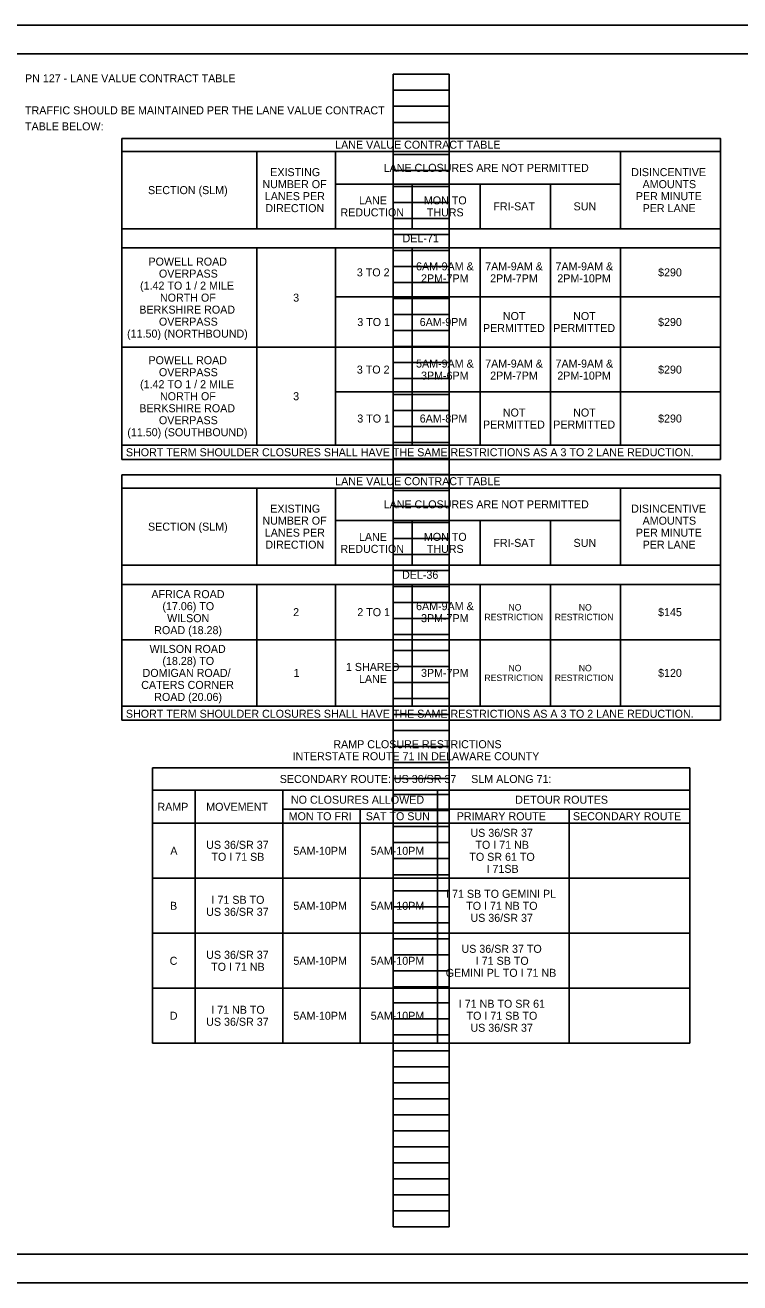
# Model space of a CAD drawing. Extents: x 0 to 34, y 0 to 22.
# Drawn here: x 9.82 to 22.33, y 0 to 22 of the extents above; entities that cross this region are included whole.
import ezdxf

# ---------------------------------------------------------------- set-up
doc = ezdxf.new("R2010")
doc.units = 0
for name, color, linetype in [('Default', 7, 'Continuous'), ('SH_Border', 7, 'Continuous'), ('SH_Cut_Line', 7, 'Continuous'), ('SH_Data', 7, 'Continuous')]:
    doc.layers.add(name, color=color, linetype=linetype)

msp = doc.modelspace()

# ---------------------------------------------------------------- linework, layer by layer
at = {"layer": 'Default'}
for p, q in [((11.511, 19.789), (21.989, 19.789)), ((13.878, 19.789), (13.878, 18.44)), ((15.254, 19.789), (15.254, 18.44)), ((20.242, 19.789), (20.242, 18.44)), ((15.254, 19.22), (20.242, 19.22)), ((16.593, 19.22), (16.593, 18.44)), ((17.783, 19.22), (17.783, 18.44)), ((19.012, 19.22), (19.012, 18.44)), ((11.511, 18.44), (21.989, 18.44)), ((11.511, 18.103), (11.511, 14.404)), ((13.878, 18.103), (13.878, 14.653)), ((15.254, 18.103), (15.254, 14.653)), ((16.593, 18.103), (16.593, 14.653)), ((17.783, 18.103), (17.783, 14.653)), ((19.012, 18.103), (19.012, 14.653)), ((20.242, 18.103), (20.242, 14.653)), ((21.989, 18.103), (21.989, 14.404)), ((15.254, 17.249), (21.989, 17.249)), ((11.511, 16.365), (21.989, 16.365)), ((15.254, 15.585), (21.989, 15.585)), ((11.511, 14.653), (21.989, 14.653)), ((11.511, 14.404), (21.989, 14.404)), ((11.511, 13.903), (21.989, 13.903)), ((13.878, 13.903), (13.878, 12.554)), ((15.254, 13.903), (15.254, 12.554)), ((20.242, 13.903), (20.242, 12.554)), ((15.254, 13.333), (20.242, 13.333)), ((16.593, 13.333), (16.593, 12.554)), ((17.783, 13.333), (17.783, 12.554)), ((19.012, 13.333), (19.012, 12.554)), ((11.511, 12.554), (21.989, 12.554)), ((11.511, 12.217), (11.511, 9.841)), ((11.511, 12.217), (21.989, 12.217)), ((13.878, 12.217), (13.878, 10.09)), ((15.254, 12.217), (15.254, 10.09)), ((16.593, 12.217), (16.593, 10.09)), ((17.783, 12.217), (17.783, 10.09)), ((19.012, 12.217), (19.012, 10.09)), ((20.242, 12.217), (20.242, 10.09)), ((21.989, 12.217), (21.989, 9.841)), ((11.511, 11.247), (21.989, 11.247)), ((11.511, 10.09), (21.989, 10.09)), ((11.511, 10.09), (21.989, 10.09)), ((11.511, 9.841), (21.989, 9.841)), ((12.049, 9.011), (21.451, 9.011)), ((12.049, 4.191), (12.049, 9.011)), ((21.451, 9.011), (21.451, 4.191)), ((12.049, 8.617), (21.451, 8.617)), ((12.795, 8.617), (12.795, 4.191)), ((14.333, 8.617), (14.333, 4.191)), ((17.038, 8.617), (17.038, 4.191)), ((14.333, 8.286), (21.451, 8.286)), ((15.686, 8.286), (15.686, 4.191)), ((17.038, 8.286), (17.038, 4.191)), ((19.339, 8.286), (19.339, 4.191)), ((12.049, 8.038), (21.451, 8.038)), ((12.049, 7.076), (21.451, 7.076)), ((12.049, 6.114), (21.451, 6.114)), ((12.049, 5.152), (21.451, 5.152)), ((12.049, 4.191), (21.451, 4.191))]:
    msp.add_line(p, q, dxfattribs=at)
for points in [[(11.511, 20.02), (21.989, 20.02), (21.989, 18.103), (11.511, 18.103)], [(11.511, 14.134), (21.989, 14.134), (21.989, 12.217), (11.511, 12.217)]]:
    msp.add_lwpolyline(points, close=True, dxfattribs=at)
at = {"layer": 'SH_Border'}
msp.add_lwpolyline([(1.5, 21.5), (33.5, 21.5), (33.5, 0.5), (1.5, 0.5)], close=True, dxfattribs=at)
at = {"layer": 'SH_Cut_Line'}
msp.add_lwpolyline([(0, 0), (34, 0), (34, 22), (0, 22)], close=True, dxfattribs=at)
at = {"layer": 'SH_Data'}
for p, q in [((16.26, 0.98), (16.26, 21.14)), ((16.26, 21.14), (17.24, 21.14)), ((17.24, 0.98), (17.24, 21.14)), ((16.26, 20.86), (17.24, 20.86)), ((16.26, 20.58), (17.24, 20.58)), ((16.26, 20.3), (17.24, 20.3)), ((16.26, 20.02), (17.24, 20.02)), ((16.26, 19.74), (17.24, 19.74)), ((16.26, 19.46), (17.24, 19.46)), ((16.26, 19.18), (17.24, 19.18)), ((16.26, 18.9), (17.24, 18.9)), ((16.26, 18.62), (17.24, 18.62)), ((16.26, 18.34), (17.24, 18.34)), ((16.26, 18.06), (17.24, 18.06)), ((16.26, 17.78), (17.24, 17.78)), ((16.26, 17.5), (17.24, 17.5)), ((16.26, 17.22), (17.24, 17.22)), ((16.26, 16.94), (17.24, 16.94)), ((16.26, 16.66), (17.24, 16.66)), ((16.26, 16.38), (17.24, 16.38)), ((16.26, 16.1), (17.24, 16.1)), ((16.26, 15.82), (17.24, 15.82)), ((16.26, 15.54), (17.24, 15.54)), ((16.26, 15.26), (17.24, 15.26)), ((16.26, 14.98), (17.24, 14.98)), ((16.26, 14.7), (17.24, 14.7)), ((16.26, 14.42), (17.24, 14.42)), ((16.26, 14.14), (17.24, 14.14)), ((16.26, 13.86), (17.24, 13.86)), ((16.26, 13.58), (17.24, 13.58)), ((16.26, 13.3), (17.24, 13.3)), ((16.26, 13.02), (17.24, 13.02)), ((16.26, 12.74), (17.24, 12.74)), ((16.26, 12.46), (17.24, 12.46)), ((16.26, 12.18), (17.24, 12.18)), ((16.26, 11.9), (17.24, 11.9)), ((16.26, 11.62), (17.24, 11.62)), ((16.26, 11.34), (17.24, 11.34)), ((16.26, 11.06), (17.24, 11.06)), ((16.26, 10.78), (17.24, 10.78)), ((16.26, 10.5), (17.24, 10.5)), ((16.26, 10.22), (17.24, 10.22)), ((16.26, 9.94), (17.24, 9.94)), ((16.26, 9.66), (17.24, 9.66)), ((16.26, 9.38), (17.24, 9.38)), ((16.26, 9.1), (17.24, 9.1)), ((16.26, 8.82), (17.24, 8.82)), ((16.26, 8.54), (17.24, 8.54)), ((16.26, 8.26), (17.24, 8.26)), ((16.26, 7.98), (17.24, 7.98)), ((16.26, 7.7), (17.24, 7.7)), ((16.26, 7.42), (17.24, 7.42)), ((16.26, 7.14), (17.24, 7.14)), ((16.26, 6.86), (17.24, 6.86)), ((16.26, 6.58), (17.24, 6.58)), ((16.26, 6.3), (17.24, 6.3)), ((16.26, 6.02), (17.24, 6.02)), ((16.26, 5.74), (17.24, 5.74)), ((16.26, 5.46), (17.24, 5.46)), ((16.26, 5.18), (17.24, 5.18)), ((16.26, 4.9), (17.24, 4.9)), ((16.26, 4.62), (17.24, 4.62)), ((16.26, 4.34), (17.24, 4.34)), ((16.26, 4.06), (17.24, 4.06)), ((16.26, 3.78), (17.24, 3.78)), ((16.26, 3.5), (17.24, 3.5)), ((16.26, 3.22), (17.24, 3.22)), ((16.26, 2.94), (17.24, 2.94)), ((16.26, 2.66), (17.24, 2.66)), ((16.26, 2.38), (17.24, 2.38)), ((16.26, 2.1), (17.24, 2.1)), ((16.26, 1.82), (17.24, 1.82)), ((16.26, 1.54), (17.24, 1.54)), ((16.26, 1.26), (17.24, 1.26)), ((16.26, 0.98), (17.24, 0.98))]:
    msp.add_line(p, q, dxfattribs=at)

# ---------------------------------------------------------------- texts
at = {"layer": 'Default'}
for s, height, p in [('PN 127 - LANE VALUE CONTRACT TABLE', 0.14, (9.82, 21)), ('TRAFFIC SHOULD BE MAINTAINED PER THE LANE VALUE CONTRACT', 0.14, (9.82, 20.44)), ('TABLE BELOW:', 0.14, (9.82, 20.16)), ('LANE VALUE CONTRACT TABLE', 0.14, (15.247, 19.839)), ('EXISTING', 0.14, (14.111, 19.359)), ('LANE CLOSURES ARE NOT PERMITTED', 0.14, (16.095, 19.434)), ('DISINCENTIVE', 0.14, (20.426, 19.359)), ('SECTION (SLM)', 0.14, (11.972, 19.044)), ('NUMBER OF', 0.14, (13.974, 19.149)), ('AMOUNTS', 0.14, (20.626, 19.149)), ('LANES PER ', 0.14, (14.016, 18.939)), ('LANE ', 0.14, (15.663, 18.865)), ('MON TO', 0.14, (16.799, 18.865)), ('PER MINUTE', 0.14, (20.508, 18.939)), ('DIRECTION', 0.14, (14.025, 18.729)), ('REDUCTION', 0.14, (15.339, 18.655)), ('THURS', 0.14, (16.85, 18.655)), ('FRI-SAT', 0.14, (18.015, 18.76)), ('SUN', 0.14, (19.418, 18.76)), ('PER LANE', 0.14, (20.627, 18.729)), ('DEL-71', 0.14, (16.426, 18.201)), ('POWELL ROAD', 0.14, (11.98, 17.794)), ('6AM-9AM &', 0.14, (16.662, 17.711)), ('7AM-9AM &', 0.14, (17.872, 17.711)), ('7AM-9AM &', 0.14, (19.102, 17.711)), ('OVERPASS', 0.14, (12.163, 17.584)), ('3 TO 2', 0.14, (15.626, 17.606)), ('2PM-7PM', 0.14, (16.749, 17.501)), ('2PM-7PM', 0.14, (17.959, 17.501)), ('2PM-10PM', 0.14, (19.134, 17.501)), ('$290', 0.14, (20.897, 17.606)), ('(1.42 TO 1 / 2 MILE', 0.14, (11.833, 17.374)), ('NORTH OF', 0.14, (12.181, 17.164)), ('3', 0.14, (14.512, 17.164)), ('BERKSHIRE ROAD', 0.14, (11.82, 16.954)), ('NOT', 0.14, (18.181, 16.842)), ('NOT', 0.14, (19.411, 16.842)), ('OVERPASS', 0.14, (12.163, 16.744)), ('3 TO 1', 0.14, (15.634, 16.737)), ('6AM-9PM ', 0.14, (16.726, 16.737)), ('PERMITTED', 0.14, (17.833, 16.632)), ('PERMITTED', 0.14, (19.063, 16.632)), ('$290', 0.14, (20.897, 16.737)), ('(11.50) (NORTHBOUND)', 0.14, (11.606, 16.534)), ('POWELL ROAD', 0.14, (11.98, 16.069)), ('5AM-9AM &', 0.14, (16.662, 16.01)), ('7AM-9AM &', 0.14, (17.872, 16.01)), ('7AM-9AM &', 0.14, (19.102, 16.01)), ('OVERPASS', 0.14, (12.163, 15.859)), ('3 TO 2', 0.14, (15.626, 15.905)), ('3PM-6PM', 0.14, (16.749, 15.8)), ('2PM-7PM', 0.14, (17.959, 15.8)), ('2PM-10PM', 0.14, (19.134, 15.8)), ('$290', 0.14, (20.897, 15.905)), ('(1.42 TO 1 / 2 MILE', 0.14, (11.833, 15.649)), ('NORTH OF', 0.14, (12.181, 15.439)), ('3', 0.14, (14.512, 15.439)), ('BERKSHIRE ROAD', 0.14, (11.82, 15.229)), ('3 TO 1', 0.14, (15.634, 15.049)), ('6AM-8PM ', 0.14, (16.726, 15.049)), ('NOT ', 0.14, (18.181, 15.154)), ('NOT ', 0.14, (19.411, 15.154)), ('$290', 0.14, (20.897, 15.049)), ('OVERPASS', 0.14, (12.163, 15.019)), ('PERMITTED', 0.14, (17.833, 14.944)), ('PERMITTED', 0.14, (19.063, 14.944)), ('(11.50) (SOUTHBOUND)', 0.14, (11.61, 14.809)), ('SHORT TERM SHOULDER CLOSURES SHALL HAVE THE SAME RESTRICTIONS AS A 3 TO 2 LANE REDUCTION.', 0.14, (11.585, 14.459)), ('LANE VALUE CONTRACT TABLE', 0.14, (15.247, 13.953)), ('LANE CLOSURES ARE NOT PERMITTED', 0.14, (16.095, 13.548)), ('EXISTING', 0.14, (14.111, 13.473)), ('DISINCENTIVE', 0.14, (20.426, 13.473)), ('SECTION (SLM)', 0.14, (11.972, 13.158)), ('NUMBER OF', 0.14, (13.974, 13.263)), ('AMOUNTS', 0.14, (20.626, 13.263)), ('LANES PER ', 0.14, (14.016, 13.053)), ('DIRECTION', 0.14, (14.025, 12.843)), ('LANE ', 0.14, (15.663, 12.979)), ('MON TO', 0.14, (16.799, 12.979)), ('FRI-SAT', 0.14, (18.015, 12.874)), ('SUN', 0.14, (19.418, 12.874)), ('PER MINUTE', 0.14, (20.508, 13.053)), ('PER LANE', 0.14, (20.627, 12.843)), ('REDUCTION', 0.14, (15.339, 12.769)), ('THURS', 0.14, (16.85, 12.769)), ('DEL-36', 0.14, (16.417, 12.315)), ('AFRICA ROAD ', 0.14, (12.031, 11.977)), ('(17.06) TO', 0.14, (12.224, 11.767)), ('6AM-9AM &', 0.14, (16.662, 11.767)), ('WILSON ', 0.14, (12.306, 11.557)), ('2', 0.14, (14.511, 11.662)), ('2 TO 1', 0.14, (15.634, 11.662)), ('3PM-7PM', 0.14, (16.749, 11.557)), ('RESTRICTION', 0.1134, (17.858, 11.59)), ('NO', 0.1134, (18.279, 11.76)), ('RESTRICTION', 0.1134, (19.088, 11.59)), ('NO', 0.1134, (19.509, 11.76)), ('$145', 0.14, (20.897, 11.662)), ('ROAD (18.28)', 0.14, (12.081, 11.347)), ('WILSON ROAD ', 0.14, (12, 11.019)), ('(18.28) TO', 0.14, (12.224, 10.809)), ('1 SHARED', 0.14, (15.435, 10.704)), ('NO', 0.1134, (18.279, 10.697)), ('NO', 0.1134, (19.509, 10.697)), ('DOMIGAN ROAD/', 0.14, (11.877, 10.599)), ('1', 0.14, (14.519, 10.599)), ('LANE', 0.14, (15.663, 10.494)), ('3PM-7PM', 0.14, (16.749, 10.599)), ('RESTRICTION', 0.1134, (17.858, 10.527)), ('RESTRICTION', 0.1134, (19.088, 10.527)), ('$120', 0.14, (20.897, 10.599)), ('CATERS CORNER ', 0.14, (11.853, 10.389)), ('ROAD (20.06)', 0.14, (12.081, 10.179)), ('SHORT TERM SHOULDER CLOSURES SHALL HAVE THE SAME RESTRICTIONS AS A 3 TO 2 LANE REDUCTION.', 0.14, (11.585, 9.885)), ('RAMP CLOSURE RESTRICTIONS', 0.14, (15.215, 9.352)), ('INTERSTATE ROUTE 71 IN DELAWARE COUNTY', 0.14, (14.502, 9.142)), ('SECONDARY ROUTE: US 36/SR 37     SLM ALONG 71:', 0.14, (14.277, 8.744)), ('RAMP', 0.14, (12.137, 8.257)), ('MOVEMENT', 0.14, (12.99, 8.257)), ('NO CLOSURES ALLOWED', 0.14, (14.473, 8.381)), ('DETOUR ROUTES', 0.14, (18.398, 8.381)), ('MON TO FRI', 0.14, (14.433, 8.092)), ('SAT TO SUN', 0.14, (15.781, 8.092)), ('PRIMARY ROUTE', 0.14, (17.374, 8.092)), ('SECONDARY ROUTE', 0.14, (19.407, 8.092)), ('US 36/SR 37', 0.14, (17.614, 7.802)), ('US 36/SR 37', 0.14, (12.99, 7.592)), ('TO I 71 NB ', 0.14, (17.701, 7.592)), ('A', 0.14, (12.362, 7.487)), ('TO I 71 SB', 0.14, (13.082, 7.382)), ('5AM-10PM', 0.14, (14.516, 7.487)), ('5AM-10PM', 0.14, (15.869, 7.487)), ('TO SR 61 TO', 0.14, (17.595, 7.382)), ('I 71SB', 0.14, (17.895, 7.172)), ('I 71 SB TO GEMINI PL', 0.14, (17.188, 6.735)), ('B', 0.14, (12.357, 6.525)), ('I 71 SB TO', 0.14, (13.083, 6.63)), ('5AM-10PM', 0.14, (14.516, 6.525)), ('5AM-10PM', 0.14, (15.869, 6.525)), ('TO I 71 NB TO', 0.14, (17.54, 6.525)), ('US 36/SR 37', 0.14, (12.99, 6.42)), ('US 36/SR 37', 0.14, (17.614, 6.315)), ('US 36/SR 37', 0.14, (12.99, 5.668)), ('US 36/SR 37 TO', 0.14, (17.457, 5.773)), ('C', 0.14, (12.351, 5.563)), ('TO I 71 NB', 0.14, (13.077, 5.458)), ('5AM-10PM', 0.14, (14.516, 5.563)), ('5AM-10PM', 0.14, (15.869, 5.563)), ('I 71 SB TO', 0.14, (17.707, 5.563)), ('GEMINI PL TO I 71 NB', 0.14, (17.181, 5.353)), ('I 71 NB TO', 0.14, (13.078, 4.707)), ('I 71 NB TO SR 61', 0.14, (17.41, 4.812)), ('D', 0.14, (12.353, 4.602)), ('US 36/SR 37', 0.14, (12.99, 4.497)), ('5AM-10PM', 0.14, (14.516, 4.602)), ('5AM-10PM', 0.14, (15.869, 4.602)), ('TO I 71 SB TO', 0.14, (17.546, 4.602)), ('US 36/SR 37', 0.14, (17.614, 4.392))]:
    msp.add_text(s, height=height, dxfattribs=at).set_placement(p)

doc.saveas('drawing.dxf')
